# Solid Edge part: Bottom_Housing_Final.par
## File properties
Author: Chalangana Oshan
Template: iso metric part.par
Last saved by: Chalangana Oshan
Revision: 70
Application: Solid Edge
Density: 7250.000 kg/m^3
Accuracy: 0.990
Username: Nimesh.N
Material: Iron:0.6015 , EN-GJL-150
Face Style: Tan
Fill Style: ANSI31(Iron)
Virtual Style: ANSI31(Iron)
Grouping: Iron\Gray Cast Iron
LibraryName: Materials-DIN
Coef. of Thermal Exp: 1.05e-05
Thermal Conductivity: 58.0
Specific Heat: 460.0
Modulus of Elasticity: 80000000000.0
Poisson's Ratio: 0.26
Yield Stress: 100593984.0
Ultimate Stress: 150825984.0
Elongation: 0.0
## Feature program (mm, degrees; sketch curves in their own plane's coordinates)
sketch for "unnamed Protrusion 1" plane through (0, 0, 0) normal (0, -1, 0) x-axis (1, 0, 0)
  line (372.619, 154.6126) -> (96.0317, 257.6876)
  arc centre (0, 0) radius 275 from (96.0317, 257.6876) to (8.7302, -274.8614) ccw
  line (8.7302, -274.8614) -> (333.535, -264.5449)
  line (333.535, -264.5449) -> (451.0326, -93.3816)
  arc centre (315, 0) radius 165 from (451.0326, -93.3816) to (372.619, 154.6126) ccw
extrude "unnamed Protrusion 1" add finite 1140 along -normal
sketch for "unnamed Cutout 1" plane through (0, 0, 0) normal (0, -1, 0) x-axis (1, 0, 0)
  line (89.0476, 238.9467) -> (365.6349, 135.8716)
  line (434.5438, -82.0626) -> (322.7778, -244.8765)
  line (8.0952, -254.8715) -> (322.7778, -244.8765)
extrude "unnamed Cutout 1" cut through along -normal
sketch for "ExtrudedProtrusion_2" plane through (0, 0, 0) normal (0, -1, 0) x-axis (1, 0, 0)
  arc centre (315, 0) radius 265 from (201.4286, 239.4296) to (323.4127, -264.8664) cw
  line (323.4127, -264.8664) -> (-3.8692, -275.2616)
  line (-3.8692, -275.2616) -> (-115.4432, -59.7734)
  arc centre (0, 0) radius 130 from (-115.4432, -59.7734) to (-55.7143, 117.456) cw
  line (-55.7143, 117.456) -> (201.4286, 239.4296)
extrude "ExtrudedProtrusion_2" add finite 260 along +normal
sketch for "unnamed Cutout 2" plane through (0, 0, 0) normal (0, -1, 0) x-axis (1, 0, 0)
  line (8.0952, -254.8715) -> (322.7778, -244.8765)
  line (-97.6827, -50.5775) -> (8.0952, -254.8715)
  line (-47.1429, 99.3859) -> (210, 221.3594)
extrude "unnamed Cutout 2" cut through along +normal
sketch for "ExtrudedProtrusion_5" plane through (225, -260, -5.1308) normal (0, -1, 0) x-axis (0.999496, 0, 0.031746)
  arc centre (90.1175, 2.2711) radius 265 from (90.1175, -262.7289) to (-15.7957, 245.1854) ccw
  line (-15.7957, 245.1854) -> (-276.6812, 131.4366)
  arc centre (-224.7237, 12.2711) radius 130 from (-342.0063, -43.8074) to (-276.6812, 131.4366) cw
  line (-342.0063, -43.8074) -> (-237.3294, -262.7289)
  line (-237.3294, -262.7289) -> (90.1175, -262.7289)
extrude "ExtrudedProtrusion_5" add finite 20 symmetric
sketch for "ExtrudedCutout_3" plane through (-49.194, 0, 0.0147) normal (0, -1, 0) x-axis (0.937046, 0, -0.349206)
  arc centre (46.1022, 17.0164) radius 275.1487 from (46.1022, 292.1651) to (138.5997, -242.1188) ccw
  line (138.5997, -242.1188) -> (441.6478, -118.0891)
  arc centre (341.2716, 127.1651) radius 265 from (441.6478, -118.0891) to (151.2397, 311.8618) ccw
  line (151.2397, 311.8618) -> (132.096, 292.1651)
  line (132.096, 292.1651) -> (46.1022, 292.1651)
extrude "ExtrudedCutout_3" add finite 20 symmetric
sketch for "ExtrudedProtrusion_8" plane through (102.5, 1140, 0) normal (0, 1, 0) x-axis (-0.999496, 0, -0.031746)
  arc centre (102.4483, 3.254) radius 275 from (102.4483, -271.746) to (-1.7156, 257.7631) ccw
  line (-1.7156, 257.7631) -> (-274.8912, 145.9594)
  arc centre (-212.3929, -6.746) radius 165 from (-345.3924, -104.3991) to (-274.8912, 145.9594) cw
  line (-345.3924, -104.3991) -> (-222.5203, -271.746)
  line (-222.5203, -271.746) -> (102.4483, -271.746)
extrude "ExtrudedProtrusion_8" add finite 20 symmetric
sketch for "ExtrudedProtrusion_9" plane through (225, -260, -5.1308) normal (0, -1, 0) x-axis (0.999496, 0, 0.031746)
  circle centre (-224.7237, 12.2711) radius 80
extrude "ExtrudedProtrusion_9" add finite 63 symmetric  Profile_Plane1_Distance = 10 mm
sketch for "ExtrudedCutout_4" plane through (225, -260, -5.1308) normal (0, -1, 0) x-axis (0.999496, 0, 0.031746)
  circle centre (-224.7237, 12.2711) radius 60
extrude "ExtrudedCutout_4" cut finite 23 symmetric
sketch for "ExtrudedProtrusion_10" plane through (225, -260, -5.1308) normal (0, -1, 0) x-axis (0.999496, 0, 0.031746)
  circle centre (90.1175, 2.2711) radius 80
extrude "ExtrudedProtrusion_10" add finite 63 symmetric
sketch for "ExtrudedCutout_5" plane through (225, -260, -5.1308) normal (0, -1, 0) x-axis (0.999496, 0, 0.031746)
  circle centre (90.1175, 2.2711) radius 60
extrude "ExtrudedCutout_5" cut finite 23 symmetric
sketch for "ExtrudedProtrusion_11" plane through (-49.2944, 0, -0.1261) normal (0, -1, 0) x-axis (0.903508, 0, 0.428571)
  circle centre (44.5919, -21.0122) radius 65
extrude "ExtrudedProtrusion_11" add finite 58 symmetric  Profile_Plane1_Distance = 10 mm
sketch for "ExtrudedCutout_6" plane through (-49.2944, 0, -0.1261) normal (0, -1, 0) x-axis (0.903508, 0, 0.428571)
  circle centre (44.5919, -21.0122) radius 45
extrude "ExtrudedCutout_6" cut finite 18 symmetric  Profile_Plane1_Distance = 10 mm
sketch for "ExtrudedProtrusion_12" plane through (-49.2944, 0, -0.1261) normal (0, -1, 0) x-axis (0.903508, 0, 0.428571)
  circle centre (329.1969, -156.0122) radius 90
extrude "ExtrudedProtrusion_12" add finite 88 symmetric
sketch for "ExtrudedCutout_7" plane through (-49.2944, 0, -0.1261) normal (0, -1, 0) x-axis (0.903508, 0, 0.428571)
  circle centre (329.1969, -156.0122) radius 70
extrude "ExtrudedCutout_7" cut finite 48 symmetric  Profile_Plane1_Distance = 10 mm
sketch for "ExtrudedCutout_8" plane through (102.5, 1140, 0) normal (0, 1, 0) x-axis (-0.565949, 0, -0.82444)
  circle centre (58.0098, 84.5051) radius 70
extrude "ExtrudedCutout_8" add finite 67 symmetric  Profile_Plane1_Distance = 10 mm
sketch for "ExtrudedCutout_9" plane through (102.5, 1140, 0) normal (0, 1, 0) x-axis (-0.565949, 0, -0.82444)
  circle centre (58.0098, 84.5051) radius 50
extrude "ExtrudedCutout_9" cut finite 27 symmetric
sketch for "ExtrudedProtrusion_14" plane through (102.5, 1140, 0) normal (0, 1, 0) x-axis (-0.999496, 0, -0.031746)
  circle centre (-212.3929, -6.746) radius 80
extrude "ExtrudedProtrusion_14" add finite 63 symmetric  Profile_Plane1_Distance = 10 mm
sketch for "ExtrudedCutout_10" plane through (102.5, 1140, 0) normal (0, 1, 0) x-axis (-0.999496, 0, -0.031746)
  circle centre (-212.3929, -6.746) radius 60
extrude "ExtrudedCutout_10" cut finite 23 symmetric
fillet "Round_1" radius 10
fillet "Round_2" radius 5
sketch for "unnamed Cutout 3" plane through (152.5, 706.0495, 0) normal (0, 0, 1) x-axis (0, 1, 0)
  line (-3373.5207, 1611.0383) -> (899.6601, 1611.0383)
  line (899.6601, 1611.0383) -> (899.6601, -591.0415)
  line (899.6601, -591.0415) -> (-3373.5207, -591.0415)
  line (-3373.5207, -591.0415) -> (-3373.5207, 1611.0383)
extrude "unnamed Cutout 3" cut through along +normal
sketch for "ExtrudedProtrusion_16" plane through (152.1178, 442.4992, -325) normal (0, 0, 1) x-axis (0, 1, 0)
extrude "ExtrudedProtrusion_16" add through along +normal  Profile_Plane1_Distance = 325 mm
sketch for "ExtrudedProtrusion_17" plane through (152.1178, 442.4992, -325) normal (0, 0, 1) x-axis (0, 1, 0)
extrude "ExtrudedProtrusion_17" add through along +normal  Profile_Plane1_Distance = 325 mm
sketch for "ExtrudedProtrusion_18" plane through (152.1178, 442.4992, -325) normal (0, 0, 1) x-axis (0, 1, 0)
extrude "ExtrudedProtrusion_18" add through along +normal  Profile_Plane1_Distance = 325 mm
sketch for "ExtrudedCutout_13" plane through (102.5, 1004.0666, -162.5) normal (-0.001808, 0.999998, 0) x-axis (-0.999998, -0.001808, 0)
extrude "ExtrudedCutout_13" cut finite 779.5266 along -normal
sketch for "unnamed Cutout 4" plane through (225, -152.5, -162.5) normal (0.007042, -0.999975, 0) x-axis (0.999975, 0.007042, 0)
  arc centre (-255.0088, -162.5) radius 50 from (-305.0088, -162.5) to (-255.0088, -112.5) cw
  line (255.0088, -112.5) -> (-255.0088, -112.5)
  arc centre (255.0088, -162.5) radius 50 from (305.0088, -162.5) to (255.0088, -112.5) ccw
  line (-305.0088, -162.5) -> (305.0088, -162.5)
extrude "unnamed Cutout 4" cut finite 128.7427 along -normal
sketch for "unnamed Protrusion 2" plane through (-275, 983.3842, -162.5) normal (-1, 0, 0) x-axis (0, 0, -1)
  line (162.5, 30) -> (162.5, -30)
  line (162.5, -30) -> (142.5, -30)
  line (142.5, -30) -> (142.5, 30)
  line (142.5, 30) -> (162.5, 30)
  dimension (linear) = 162.5
  dimension (linear) = 142.5
extrude "unnamed Protrusion 2" add finite 60 along +normal
sketch for "ExtrudedProtrusion_20" plane through (-275, 268.7152, -162.5) normal (-1, 0, 0) x-axis (0, 0, -1)
  line (162.5, 30) -> (162.5, -30)
  line (162.5, -30) -> (142.5, -30)
  line (142.5, -30) -> (142.5, 30)
  line (142.5, 30) -> (162.5, 30)
  dimension (linear) = 162.5
  dimension (linear) = 142.5
extrude "ExtrudedProtrusion_20" add finite 60 along +normal
sketch for "unnamed Protrusion 3" plane through (-130, -135, -162.5) normal (-1, 0, 0) x-axis (0, 0, -1)
  line (162.5, 30) -> (162.5, -30)
  line (162.5, -30) -> (142.5, -30)
  line (142.5, -30) -> (142.5, 30)
  line (142.5, 30) -> (162.5, 30)
  dimension (linear) = 162.5
  dimension (linear) = 142.5
extrude "unnamed Protrusion 3" add finite 60 along +normal
sketch for "ExtrudedProtrusion_22" plane through (480, 984.0666, -162.5) normal (1, 0, 0) x-axis (0, 0, 1)
  line (-162.5, 30) -> (-162.5, -30)
  line (-162.5, -30) -> (-142.5, -30)
  line (-142.5, -30) -> (-142.5, 30)
  line (-142.5, 30) -> (-162.5, 30)
  dimension (linear) = 162.5
  dimension (linear) = 142.5
extrude "ExtrudedProtrusion_22" add finite 60 along +normal
sketch for "ExtrudedProtrusion_23" plane through (480, 268.7152, -162.5) normal (1, 0, 0) x-axis (0, 0, 1)
  line (-162.5, 30) -> (-162.5, -30)
  line (-162.5, -30) -> (-142.5, -30)
  line (-142.5, -30) -> (-142.5, 30)
  line (-142.5, 30) -> (-162.5, 30)
  dimension (linear) = 162.5
  dimension (linear) = 162.5
extrude "ExtrudedProtrusion_23" add finite 60 along +normal
sketch for "ExtrudedProtrusion_24" plane through (580, -130, -162.5) normal (1, 0, 0) x-axis (0, 0, 1)
  line (-162.5, 30) -> (-162.5, -30)
  line (-162.5, -30) -> (-142.5, -30)
  line (-142.5, -30) -> (-142.5, 30)
  line (-142.5, 30) -> (-162.5, 30)
  dimension (linear) = 162.5
  dimension (linear) = 142.5
  dimension (linear) = 142.5
extrude "ExtrudedProtrusion_24" add finite 60 along +normal
sketch for "ExtrudedCutout_16" plane through (315, 1128.5, -35) normal (0, 1, 0) x-axis (1, 0, 0)
extrude "ExtrudedCutout_16" cut finite 1400 along -normal
sketch for "ExtrudedProtrusion_25" plane through (102.5, 1140, -132.5) normal (0, 1, 0) x-axis (-1, 0, 0)
  circle centre (-130.08, -4.64) radius 80
extrude "ExtrudedProtrusion_25" add finite 63 symmetric  Profile_Plane1_Distance = 10 mm
sketch for "unnamed Cutout 5" plane through (232.58, 1108.5, -137.14) normal (0, -1, 0) x-axis (0, 0, 1)
  circle centre (0, 0) radius 60
extrude "unnamed Cutout 5" cut to key point along -normal
fillet "Round_3" radius 5
fillet "Round_4" radius 5
sketch for "ExtrudedProtrusion_27" plane through (-154.1322, 441, -276.5) normal (0, 0, 1) x-axis (0, 1, 0)
extrude "ExtrudedProtrusion_27" add through along +normal  Profile_Plane1_Distance = 276.5 mm
sketch for "unnamed Cutout 6" plane through (8.0952, 660.5641, -276.5) normal (0, 0, -1) x-axis (0, -1, 0)
extrude "unnamed Cutout 6" cut through along -normal
sketch for "ExtrudedProtrusion_32" plane through (630, -123.3295, -152.5) normal (1, 0, 0) x-axis (0, 0, 1)
  line (152.5, -133.3295) -> (152.5, 26.6705)
  line (152.5, 146.6705) -> (152.5, 26.6705)
  line (142.5, 146.6705) -> (152.5, 146.6705)
  line (142.5, -123.3295) -> (142.5, 146.6705)
  line (142.5, -123.3295) -> (142.5, -133.3295)
  line (142.5, -133.3295) -> (152.5, -133.3295)
extrude "ExtrudedProtrusion_32" add through along -normal  Profile_Plane1_Distance = 50 mm
sketch for "unnamed Cutout 7" plane through (0, 29, -30) normal (0, 1, 0) x-axis (-1, 0, 0)
extrude "unnamed Cutout 7" cut through along -normal
sketch for "ExtrudedProtrusion_34" plane through (530, 268.7152, -152.5) normal (1, 0, 0) x-axis (0, 0, 1)
extrude "ExtrudedProtrusion_34" add through along -normal  Profile_Plane1_Distance = 50 mm
sketch for "ExtrudedProtrusion_35" plane through (-325, 268.7152, -152.5) normal (-1, 0, 0) x-axis (0, 0, -1)
  line (-152.5, 278.7152) -> (-142.5, 278.7152)
  line (-142.5, 278.7152) -> (-142.5, -881.2848)
  line (-142.5, -881.2848) -> (-152.5, -881.2848)
  line (-152.5, -881.2848) -> (-152.5, 278.7152)
  dimension (linear) = 152.5
extrude "ExtrudedProtrusion_35" add through along -normal  Profile_Plane1_Distance = 50 mm
sketch for "ExtrudedProtrusion_36" plane through (-180, -135, -152.5) normal (-1, 0, 0) x-axis (0, 0, -1)
extrude "ExtrudedProtrusion_36" add through along -normal  Profile_Plane1_Distance = 50 mm
sketch for "unnamed Cutout 8" plane through (225, -10, -127.4357) normal (0, -1, 0) x-axis (1, 0, 0)
extrude "unnamed Cutout 8" cut to key point along -normal
fillet "Round_14" radius 5
sketch for "unnamed Cutout 9" plane through (-300, 983.3842, -305) normal (0, 0, 1) x-axis (0, -1, 0)
extrude "unnamed Cutout 9" cut through along -normal
sketch for "unnamed Cutout 10" plane through (-305, 268.7152, -305) normal (0, 0, 1) x-axis (0, -1, 0)
extrude "unnamed Cutout 10" cut through along -normal
sketch for "unnamed Cutout 11" plane through (-160, -135, -305) normal (0, 0, 1) x-axis (0, -1, 0)
  circle centre (0, 0) radius 15
extrude "unnamed Cutout 11" cut through along -normal
sketch for "unnamed Cutout 12" plane through (510, 984.0666, -305) normal (0, 0, 1) x-axis (0, 1, 0)
extrude "unnamed Cutout 12" cut through along -normal
sketch for "unnamed Cutout 13" plane through (510, 268.7152, -305) normal (0, 0, 1) x-axis (0, 1, 0)
extrude "unnamed Cutout 13" cut through along -normal
sketch for "unnamed Cutout 14" plane through (610, -130, -305) normal (0, 0, 1) x-axis (0, 1, 0)
extrude "unnamed Cutout 14" cut through along -normal
fillet "Round_15" radius 10
fillet "Round_17" radius 5
thread "unnamed Thread 1"
sketch for "unnamed Protrusion 4" plane through (480, 983.3129, -157.5) normal (1, 0, 0) x-axis (0, 0, -1)
  circle centre (0, -5) radius 15
extrude "unnamed Protrusion 4" add through along -normal
sketch for "ExtrudedCutout_44" plane through (480, 750, -232.5449) normal (1, 0, 0) x-axis (0, 1, 0)
extrude "ExtrudedCutout_44" cut finite 166.4875 along -normal
sketch for "unnamed Cutout 15" plane through (379.067, 750, -232.5449) normal (1, 0, 0) x-axis (0, 1, 0)
extrude "unnamed Cutout 15" cut through along +normal
thread "unnamed Thread 2"
sketch for "ExtrudedProtrusion_42" plane through (225, -320, -132.5333) normal (0, -1, 0) x-axis (1, 0, 0)
  line (405, 132.5333) -> (405, 122.5333)
  line (405, 122.5333) -> (-405, 122.5333)
  line (-405, 122.5333) -> (-405, 132.5333)
  line (-405, 132.5333) -> (405, 132.5333)
extrude "ExtrudedProtrusion_42" add through along -normal  Profile_Plane1_Distance = 50 mm
sketch for "ExtrudedProtrusion_43" plane through (102.5, 1197, -132.5) normal (0, 1, 0) x-axis (-1, 0, 0)
  line (427.5, 132.5) -> (427.5, 122.5)
  line (427.5, 122.5) -> (-427.5, 122.5)
  line (-427.5, 122.5) -> (-427.5, 132.5)
  line (-427.5, 132.5) -> (427.5, 132.5)
extrude "ExtrudedProtrusion_43" add through along -normal  Profile_Plane1_Distance = 47 mm
sketch for "unnamed Cutout 16" plane through (0, 1106.5, -32.5) normal (0, -1, 0) x-axis (1, 0, 0)
  circle centre (0, 32.5) radius 40
extrude "unnamed Cutout 16" cut through along -normal
sketch for "unnamed Cutout 17" plane through (0, -228.5, -37.5) normal (0, 1, 0) x-axis (-1, 0, 0)
  circle centre (0, 37.5) radius 32.5
extrude "unnamed Cutout 17" cut through along -normal
fillet "Round_19" radius 40
sketch for "unnamed Cutout 18" plane through (0, -291.5, -42.5) normal (0, -1, 0) x-axis (1, 0, 0)
  circle centre (0, 42.5) radius 80
extrude "unnamed Cutout 18" cut through along +normal
sketch for "unnamed Cutout 19" plane through (0, 1173.5, -37.5) normal (0, 1, 0) x-axis (-1, 0, 0)
  circle centre (0, 37.5) radius 86.5
extrude "unnamed Cutout 19" cut through along +normal
fillet "Round_22" radius 25
fillet "Round_23" radius 3
Other named dimensions: "ExtrudedSurface_1": FiniteDepth = 1412.0989 mm
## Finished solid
Body 1: sheet body, 1 face, 4 edges, 4 vertices.
  Faces by surface: plane 1
  Edges by curve: line 4
Body 2: sheet body, 1 face, 4 edges, 4 vertices.
  Faces by surface: plane 1
  Edges by curve: line 4
Body 3: solid body, 287 faces, 785 edges, 490 vertices.
  Faces by surface: plane 132, cylinder 111, torus 38, blend 6
  Edges by curve: line 446, circle 261, intersection 53, ellipse 25
Bounding box of the edges (mm; curved faces can reach further): 975.000 x 1915.756 x 325.000, from (-335, -503.6574, -325) to (640, 1412.0989, 0).
Cylindrical faces by radius (mm): R3 x12, R5 x20, R10 x10, R15 x7, R25 x1, R32.5 x6, R40 x10, R40.75 x1, R45 x1, R50 x7, R60 x4, R65 x2, R70 x3, R80 x10, R90 x2, R110 x1, R130 x2, R145 x1, R165 x3, R245 x1, R255 x1, R265 x2, R275 x3, R275.1487 x1
Toroidal faces (ring radius, tube radius in mm): R37 r3 x6, R43 r3 x2, R60 r5 x2, R65 r5 x2, R75 r5 x8, R85 r5 x2, R105 r25 x2, R111.455 r25 x2, R120 r10 x1, R155 r10 x1, R175 r10 x3, R255 r10 x2, R265 r10 x1, R265.1487 r10 x1, R285 r10 x3
Planar faces by outward normal: +x 15, +y 29, +z 8, -x 14, -y 31, -z 14, oblique 21
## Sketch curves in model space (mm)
line (8.0952, 0, -254.8715) -> (322.7778, 0, -244.8765)
line (8.0952, 0, -254.8715) -> (322.7778, 0, -244.8765)
circle centre (0, 0, 0) radius 90
circle centre (0, 0, 0) radius 235
circle centre (315, 0, 0) radius 125
line (0, 0, 0) -> (-275, 0, 0)
line (0, 0, 0) -> (315, 0, 0)
line (315, 0, 0) -> (580, 0, 0)
line (323.4127, 0, -264.8664) -> (-3.8692, 0, -275.2616)
line (-3.8692, 0, -275.2616) -> (-115.4432, 0, -59.7734)
arc centre (0, 0, 0) radius 130 from (-115.4432, 0, -59.7734) through (-121.9033, 0, 45.1617) to (-55.7143, 0, 117.456)
line (-55.7143, 0, 117.456) -> (201.4286, 0, 239.4296)
arc centre (315, 0, 0) radius 265 from (201.4286, 0, 239.4296) through (572.5718, 0, 62.304) to (323.4127, 0, -264.8664)
line (333.535, 0, -264.5449) -> (451.0326, 0, -93.3816)
arc centre (315, 0, 0) radius 165 from (451.0326, 0, -93.3816) through (470.799, 0, 54.3293) to (372.619, 0, 154.6126)
line (372.619, 0, 154.6126) -> (96.0317, 0, 257.6876)
arc centre (0, 0, 0) radius 275 from (96.0317, 0, 257.6876) through (-272.587, 0, 36.3502) to (8.7302, 0, -274.8614)
line (8.7302, 0, -274.8614) -> (333.535, 0, -264.5449)
arc centre (315, 0, 0) radius 245 from (210, 0, 221.3594) through (553.1324, 0, 57.6018) to (322.7778, 0, -244.8765)
line (-97.6827, 0, -50.5775) -> (8.0952, 0, -254.8715)
arc centre (0, 0, 0) radius 110 from (-97.6827, 0, -50.5775) through (-103.149, 0, 38.2137) to (-47.1429, 0, 99.3859)
line (-47.1429, 0, 99.3859) -> (210, 0, 221.3594)
line (434.5438, 0, -82.0626) -> (322.7778, 0, -244.8765)
arc centre (315, 0, 0) radius 145 from (365.6349, 0, 135.8716) through (454.4742, 0, 39.6476) to (434.5438, 0, -82.0626)
arc centre (0, 0, 0) radius 255 from (8.0952, 0, -254.8715) through (-250.2947, 0, 48.7604) to (89.0476, 0, 238.9467)
line (89.0476, 0, 238.9467) -> (365.6349, 0, 135.8716)
line (0, 0, 0) -> (315, 0, 0)
circle centre (315, 0, 0) radius 225
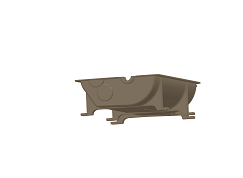
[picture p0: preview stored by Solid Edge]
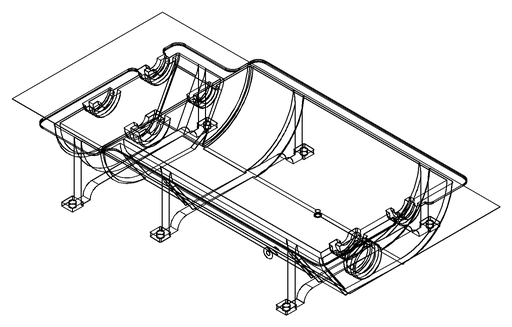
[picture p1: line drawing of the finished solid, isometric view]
